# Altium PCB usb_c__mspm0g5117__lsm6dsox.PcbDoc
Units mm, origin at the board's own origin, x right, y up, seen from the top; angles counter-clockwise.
Board outline 92 x 60 mm, 2 copper layers (Top, Bottom), stack 0 mm thick; 35 components, 28 nets, 186 pads, 77 vias.
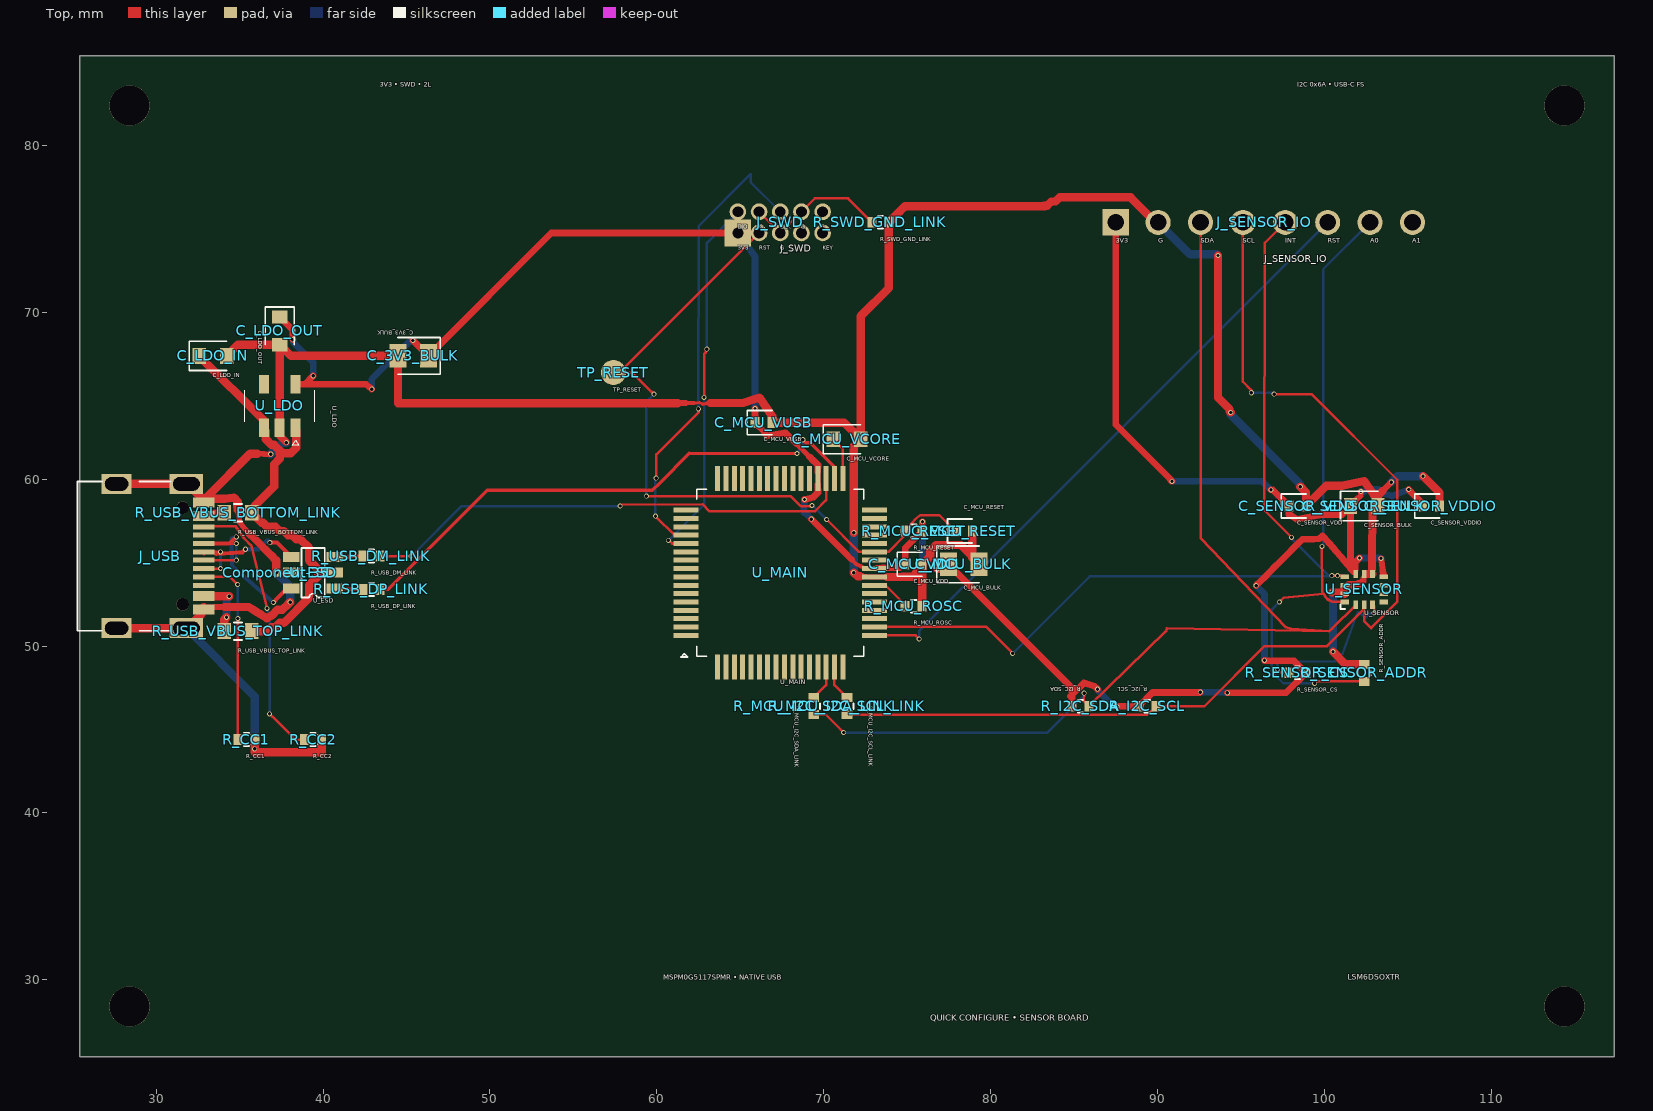
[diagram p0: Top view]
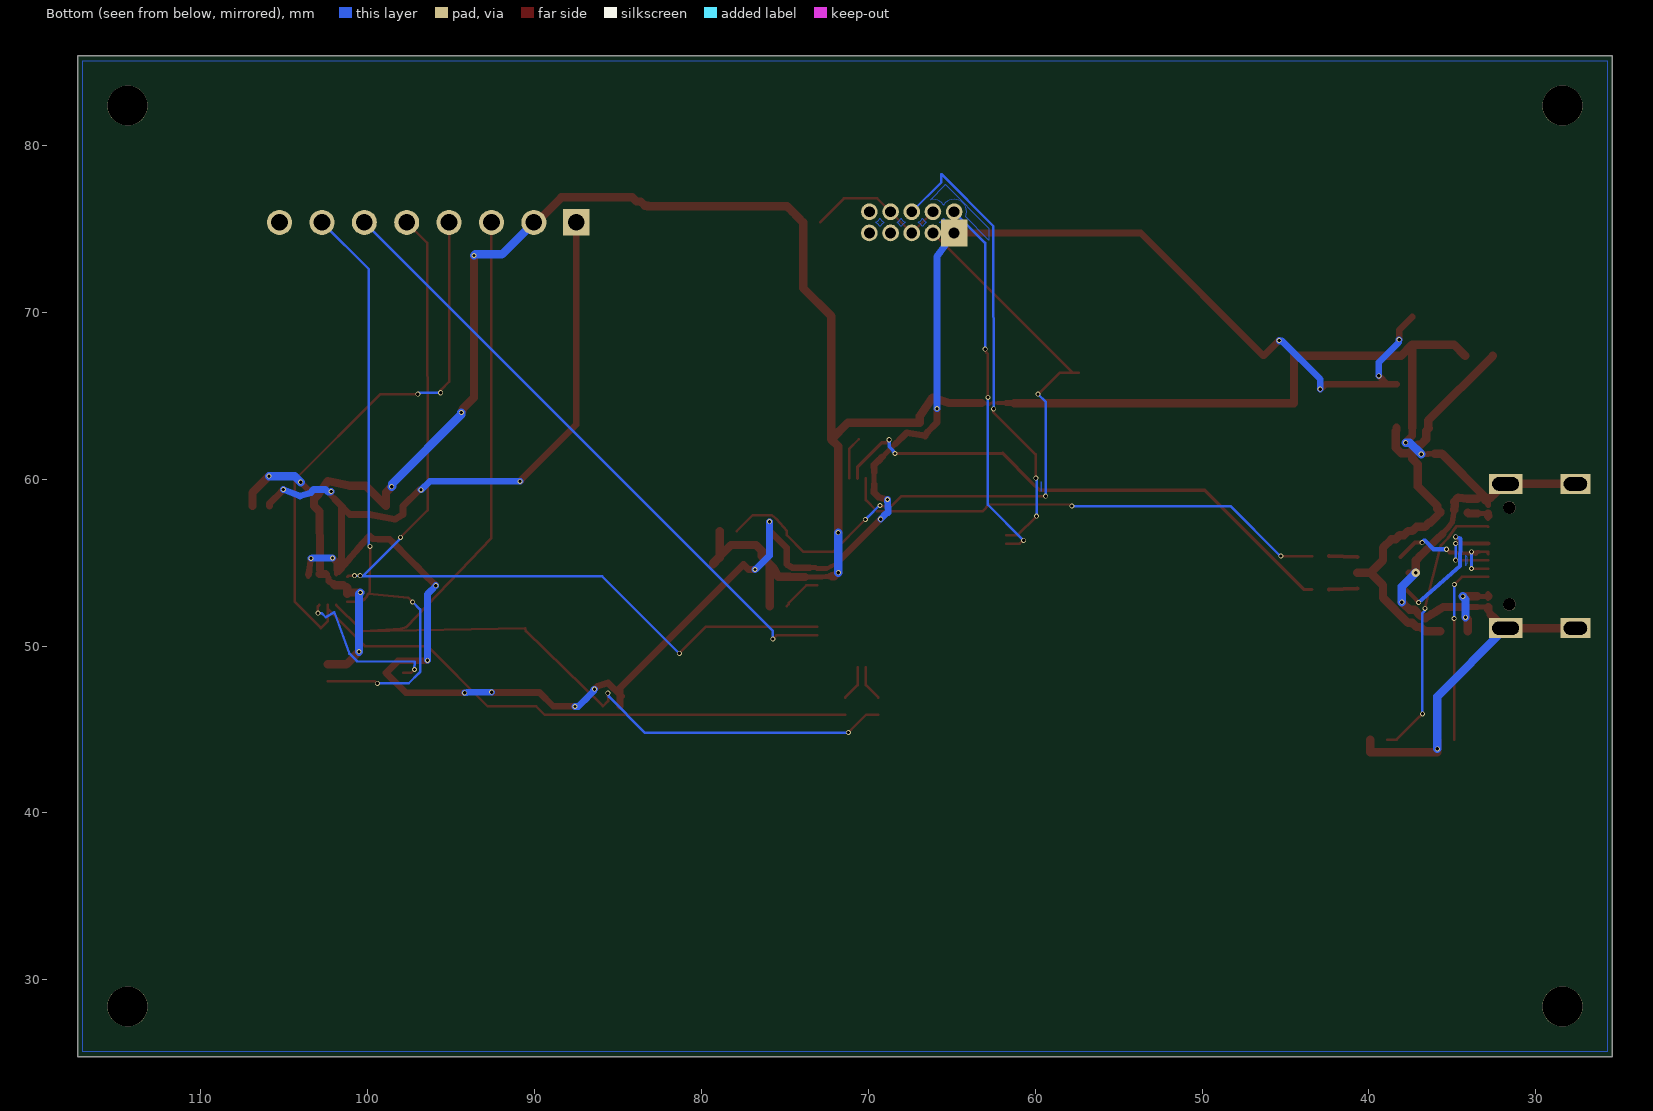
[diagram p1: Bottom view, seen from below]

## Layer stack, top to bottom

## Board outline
25.4,85.4 117.4,85.4 117.4,25.4 25.4,25.4

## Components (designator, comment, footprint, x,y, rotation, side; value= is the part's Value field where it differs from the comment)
C_3V3_BULK "" TSCIRCUIT-2.8500x1.4000mm 45.4,67.4 r180 top
C_LDO_IN "" TSCIRCUIT-2.4500x0.9500mm 33.4,67.4 r0 top
C_LDO_OUT "" TSCIRCUIT-0.9500x2.4500mm 37.4,68.9 r270 top
C_MCU_BULK "" TSCIRCUIT-2.8500x1.4000mm 78.4,54.9 r0 top
C_MCU_RESET "" TSCIRCUIT-1.5600x0.6400mm 78.4,56.9 r0 top
C_MCU_VCORE "" TSCIRCUIT-2.4500x0.9500mm 71.4,62.4 r0 top
C_MCU_VDD "" TSCIRCUIT-1.5600x0.6400mm 75.4,54.9 r0 top
C_MCU_VUSB "" TSCIRCUIT-1.5600x0.6400mm 66.4,63.4 r0 top
C_SENSOR_BULK "" TSCIRCUIT-2.4500x0.9500mm 102.4,58.4 r0 top
C_SENSOR_VDD "" TSCIRCUIT-1.5600x0.6400mm 98.4,58.4 r0 top
C_SENSOR_VDDIO "" TSCIRCUIT-1.5600x0.6400mm 106.4,58.4 r0 top
Component-35 "" TSCIRCUIT-0.5000x0.5000mm 37.2,54.4 r0 top
J_SENSOR_IO "" TSCIRCUIT-19.2800x1.5000mm 96.4,75.4 r0 top
J_SWD "" TSCIRCUIT-6.0800x2.2700mm 67.4,75.4 r0 top
J_USB "" TSCIRCUIT-6.7732x9.8502mm 30.113,55.4 r90 top
R_CC1 "" TSCIRCUIT-1.5600x0.6400mm 35.4,44.4 r0 top
R_CC2 "" TSCIRCUIT-1.5600x0.6400mm 39.4,44.4 r0 top
R_I2C_SCL "" TSCIRCUIT-1.5600x0.6400mm 89.4,46.4 r180 top
R_I2C_SDA "" TSCIRCUIT-1.5600x0.6400mm 85.4,46.4 r180 top
R_MCU_I2C_SCL_LINK "" TSCIRCUIT-0.6400x1.5600mm 71.4,46.4 r270 top
R_MCU_I2C_SDA_LINK "" TSCIRCUIT-0.6400x1.5600mm 69.4,46.4 r270 top
R_MCU_RESET "" TSCIRCUIT-1.5600x0.6400mm 75.4,56.9 r0 top
R_MCU_ROSC "" TSCIRCUIT-1.5600x0.6400mm 75.4,52.4 r0 top
R_SENSOR_ADDR "" TSCIRCUIT-0.6400x1.5600mm 102.4,48.4 r90 top
R_SENSOR_CS "" TSCIRCUIT-1.5600x0.6400mm 98.4,48.4 r0 top
R_SWD_GND_LINK "" TSCIRCUIT-1.5600x0.6400mm 73.4,75.4 r0 top
R_USB_DM_LINK "" TSCIRCUIT-1.5600x0.6400mm 42.9,55.4 r0 top
R_USB_DP_LINK "" TSCIRCUIT-1.5600x0.6400mm 42.9,53.4 r0 top
R_USB_VBUS_BOTTOM_LINK "" TSCIRCUIT-2.4500x0.9500mm 34.9,58 r0 top
R_USB_VBUS_TOP_LINK "" TSCIRCUIT-2.4500x0.9500mm 34.9,50.9 r0 top
TP_RESET "" TSCIRCUIT-1.5000x1.5000mm 57.4,66.4 r0 top
U_ESD "" TSCIRCUIT-3.6000x2.5000mm 39.4,54.4 r0 top
U_LDO "" TSCIRCUIT-2.5000x3.7000mm 37.4,64.4 r270 top
U_MAIN "" TSCIRCUIT-12.8000x12.8000mm 67.4,54.4 r0 top
U_SENSOR "" TSCIRCUIT-2.8499x2.3500mm 102.4,53.4 r0 top

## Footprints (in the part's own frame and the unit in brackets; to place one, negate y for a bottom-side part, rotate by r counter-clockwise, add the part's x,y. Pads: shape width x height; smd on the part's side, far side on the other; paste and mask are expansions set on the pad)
TSCIRCUIT-0.5000x0.5000mm [mm]
TSCIRCUIT-0.6400x1.5600mm [mm]
  rect 0.54x0.64 smd: 1(-0.51,0) 2(0.51,0)
  silkscreen extent -0.15,-0.38 0.15,0.38
TSCIRCUIT-0.9500x2.4500mm [mm]
  rect 0.8x0.95 smd: 1(-0.825,0) 2(0.825,0)
  silkscreen extent -1.43,-0.87 0.82,0.88
TSCIRCUIT-1.5000x1.5000mm [mm]
  round 1.5 smd: 1(0,0)
TSCIRCUIT-1.5600x0.6400mm [mm]
  rect 0.54x0.64 smd: 1(-0.51,0) 2(0.51,0)
  silkscreen extent -0.98,-0.72 0.51,0.72
TSCIRCUIT-2.4500x0.9500mm [mm]
  rect 0.8x0.95 smd: 1(-0.825,0) 2(0.825,0)
  silkscreen extent -1.42,-0.87 0.82,0.87
TSCIRCUIT-2.5000x3.7000mm [mm]
  rect 1.1x0.6 smd: 1(1.3,0.95) 2(1.3,0) 3(1.3,-0.95) 4(-1.3,-0.95) 5(-1.3,0.95)
  silkscreen extent -0.95,-2.1 2.35,2.1
TSCIRCUIT-2.8499x2.3500mm [mm]
  rect 0.5x0.28 smd: 1(-1.175,-0.75) 2(-1.175,-0.25) 3(-1.175,0.25) 4(-1.175,0.75) 8(1.175,0.75) 9(1.175,0.25) 10(1.175,-0.25) 11(1.175,-0.75)
  rect 0.28x0.5 smd: 5(-0.5,0.925) 6(0,0.925) 7(0.5,0.925) 12(0.5,-0.925) 13(0,-0.925) 14(-0.5,-0.925)
  silkscreen extent -1.42,-1.17 -1.14,-0.89
TSCIRCUIT-2.8500x1.4000mm [mm]
  rect 1.025x1.4 smd: 1(-0.913,0) 2(0.913,0)
  silkscreen extent -1.63,-1.1 0.91,1.1
TSCIRCUIT-3.6000x2.5000mm [mm]
  rect 1x0.6 smd: 1(-1.3,-0.95) 2(-1.3,0) 3(-1.3,0.95) 4(1.3,0.95) 5(1.3,0) 6(1.3,-0.95)
  silkscreen extent -0.7,-1.49 0.7,1.49
TSCIRCUIT-6.0800x2.2700mm [mm]
  rect 1.6x1.6 hole 0.65: 1(-2.54,-0.635)
  round 1 hole 0.65: 2(-2.54,0.635) 3(-1.27,0.635) 4(0,0.635) 5(1.27,0.635) 6(2.54,0.635) 7(2.54,-0.635) 8(1.27,-0.635) 9(0,-0.635) 10(-1.27,-0.635)
TSCIRCUIT-6.7732x9.8502mm [mm]
  rect 0.3x1.3 smd: 1(-3.35,-2.737) 2(-3.05,-2.737) 3(-2.55,-2.737) 4(-2.25,-2.737) 5(-1.75,-2.737) 6(-1.25,-2.737) 7(-0.75,-2.737) 8(-0.25,-2.737) 9(0.25,-2.737) 10(0.75,-2.737) 11(1.25,-2.737) 12(1.75,-2.737) 13(2.55,-2.737) 14(2.25,-2.737) 15(3.35,-2.737) 16(3.05,-2.737)
  rect 1.2x2 hole 0.8 slot 1.6 at 90 deg: 17(-4.325,-1.693) 18(4.325,-1.693)
  rect 1.2x1.8 hole 0.8 slot 1.4 at 90 deg: 19(4.325,2.487) 20(-4.325,2.487)
  round 0.75 hole 0.75 unplated: NPTH-1(-2.9,-1.468) NPTH-2(2.9,-1.468)
  silkscreen extent -4.47,-0.75 4.47,4.83
TSCIRCUIT-12.8000x12.8000mm [mm]
  rect 1.5x0.3 smd: 1(-5.65,-3.75) 2(-5.65,-3.25) 3(-5.65,-2.75) 4(-5.65,-2.25) 5(-5.65,-1.75) 6(-5.65,-1.25) 7(-5.65,-0.75) 8(-5.65,-0.25) 9(-5.65,0.25) 10(-5.65,0.75) 11(-5.65,1.25) 12(-5.65,1.75) 13(-5.65,2.25) 14(-5.65,2.75) 15(-5.65,3.25) 16(-5.65,3.75) 33(5.65,3.75) 34(5.65,3.25) 35(5.65,2.75) 36(5.65,2.25) 37(5.65,1.75) 38(5.65,1.25) 39(5.65,0.75) 40(5.65,0.25) 41(5.65,-0.25) 42(5.65,-0.75) 43(5.65,-1.25) 44(5.65,-1.75) 45(5.65,-2.25) 46(5.65,-2.75) 47(5.65,-3.25) 48(5.65,-3.75)
  rect 0.3x1.5 smd: 17(-3.75,5.65) 18(-3.25,5.65) 19(-2.75,5.65) 20(-2.25,5.65) 21(-1.75,5.65) 22(-1.25,5.65) 23(-0.75,5.65) 24(-0.25,5.65) 25(0.25,5.65) 26(0.75,5.65) 27(1.25,5.65) 28(1.75,5.65) 29(2.25,5.65) 30(2.75,5.65) 31(3.25,5.65) 32(3.75,5.65) 49(3.75,-5.65) 50(3.25,-5.65) 51(2.75,-5.65) 52(2.25,-5.65) 53(1.75,-5.65) 54(1.25,-5.65) 55(0.75,-5.65) 56(0.25,-5.65) 57(-0.25,-5.65) 58(-0.75,-5.65) 59(-1.25,-5.65) 60(-1.75,-5.65) 61(-2.25,-5.65) 62(-2.75,-5.65) 63(-3.25,-5.65) 64(-3.75,-5.65)
  silkscreen extent -5.95,-5.05 5,5
TSCIRCUIT-19.2800x1.5000mm [mm]
  rect 1.6x1.6 hole 1: 1(-8.89,0)
  round 1.5 hole 1: 2(-6.35,0) 3(-3.81,0) 4(-1.27,0) 5(1.27,0) 6(3.81,0) 7(6.35,0) 8(8.89,0)

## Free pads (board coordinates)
  round 2.4 hole 2.4 unplated: NPTH-3(28.4,28.4) NPTH-4(114.4,28.4) NPTH-5(28.4,82.4) NPTH-6(114.4,82.4)

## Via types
v1: diameter 0.3, hole 0.2, Top to Bottom, 76 vias
v2: diameter 0.5, hole 0.2, Top to Bottom, 1 vias

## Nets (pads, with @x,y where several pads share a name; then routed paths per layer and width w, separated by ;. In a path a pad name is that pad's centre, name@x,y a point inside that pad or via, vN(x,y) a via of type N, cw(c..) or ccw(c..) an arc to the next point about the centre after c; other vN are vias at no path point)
".J_SWD > .pin2 to .U_MAIN > .pin12": J_SWD.2 U_MAIN.12 | length 22.6
  Top w0.15: v1(60.695,56.338) 60.751,56.282 60.805,56.282 60.937,56.15 U_MAIN.12 ; v1(62.834,64.909) 62.831,67.499 62.93,67.599 62.93,67.73 v1(63,67.8)
  Bottom w0.15: v1(60.695,56.338) 62.831,58.474 62.835,64.87 v1(62.834,64.909) ; v1(63,67.8) 63,74.175 J_SWD.2
".J_SWD > .pin4 to .U_MAIN > .pin13": J_SWD.4 U_MAIN.13 | length 28.2
  Top w0.15: v1(59.922,57.788) 59.964,57.746 61.06,56.65 U_MAIN.13 ; v1(59.963,60.073) 59.977,61.488 62.5,64.012 v1(62.493,64.228)
  Bottom w0.15: v1(59.922,57.788) 59.922,59.975 59.966,60.019 59.966,60.048 v1(59.963,60.073) ; v1(62.493,64.228) 62.5,75.17 65.628,78.297 65.628,77.807 J_SWD.4
".U_MAIN > .pin42 to .R_MCU_ROSC > .pin1": R_MCU_ROSC.1 U_MAIN.42 | length 2.4
  Top w0.15: U_MAIN.42 73.719,53.65 74.769,52.6 74.769,52.521 R_MCU_ROSC.1
GND: C_3V3_BULK.2 C_LDO_IN.2 C_LDO_OUT.2 C_MCU_BULK.2 C_MCU_RESET.2 C_MCU_VCORE.2 C_MCU_VDD.2 C_MCU_VUSB.2 C_SENSOR_BULK.2 C_SENSOR_VDD.2 C_SENSOR_VDDIO.2 J_SENSOR_IO.2 J_USB.1 J_USB.2 J_USB.15 J_USB.16 J_USB.17 J_USB.18 J_USB.19 J_USB.20 R_CC1.2 R_CC2.2 R_MCU_ROSC.2 R_SENSOR_ADDR.2 R_SWD_GND_LINK.2 U_ESD.2 U_LDO.2 U_MAIN.41 U_SENSOR.2 U_SENSOR.3 U_SENSOR.6 U_SENSOR.7 | length 197.9
  Top w0.2: 62.225,64.568 62.55,64.6 62.75,64.5
  Top w0.225: 61.736,64.567 62.225,64.568 ; 62.75,64.5 63.203,64.569
  Top w0.275: J_USB.16 J_USB.15@33.04,58.641
  Top w0.28: U_SENSOR.2@100.975,53.218 101.157,53.218 U_SENSOR.2 ; U_SENSOR.3@101.225,53.51 U_SENSOR.3 101.475,53.65 ; U_SENSOR.6@102.363,54.075 U_SENSOR.6 U_SENSOR.6@102.54,54.325 ; U_SENSOR.7@102.865,54.575 102.865,54.36 U_SENSOR.7
  Top w0.3: J_USB.1@32.699,51.9 J_USB.1 J_USB.1@32.849,52.2 ; J_USB.15@32.699,58.9 J_USB.15 ; J_USB.2 J_USB.2@32.946,52.332 ; J_USB.16@32.849,58.6 J_USB.15 ; J_USB.15@32.999,58.9 J_USB.15 ; J_USB.2@33.037,52.35 33.13,52.35 33.224,52.35 33.318,52.35 33.412,52.35 33.499,52.35 ; J_USB.15@33.04,58.641 33.231,58.832 33.499,58.832 ; 72.3,54.18 72.425,54.18 72.55,54.18 72.775,54.15 U_MAIN.41 73.144,54.15 73.237,54.15 73.331,54.15 73.425,54.15 73.519,54.15 73.612,54.15 73.706,54.15 U_MAIN.41@73.8,54.15
  Top w0.301: J_USB.2@32.946,52.332 J_USB.2@33.037,52.35
  Top w0.325: J_USB.16 J_USB.16@32.849,58.6 ; 34.89,58.16 34.942,57.796 34.994,57.431 35.262,57.068 35.582,56.747
  Top w0.35: 36.051,61.533 36.457,61.518 v1(36.862,61.504) ; 61.247,64.567 61.736,64.567 ; 103.49,59.29 103.755,59.555 v1(104.029,59.829)
  Top w0.375: 33.499,52.35 33.505,52.35 33.599,52.35 34.083,52.349 ; v1@37.75,62.25 v1(37.8,62.2) ; 102.337,53.9 U_SENSOR.6@102.363,54.075
  Top w0.4: 37.2,54.4 U_ESD.2@37.6,54.4 ; 72.175,54.18 72.3,54.18 ; 102.043,53.723 102.337,53.9
  Top w0.45: 35.582,56.747 35.903,56.427 36.224,56.106 36.544,55.785 ; U_LDO.2 37.4,62.6 v1@37.75,62.25
  Top w0.475: 34.083,52.349 34.568,52.347 ; 36.544,55.785 36.865,55.464 ; U_MAIN.41@73.8,54.15 74.253,54.15 74.707,54.15
  Top w0.5: J_USB.20 J_USB.17 31.874,51.075 32.474,51.675 32.699,51.9 ; J_USB.19 J_USB.18 31.874,59.725 32.474,59.125 32.699,58.9 ; J_USB.1@32.849,52.2 J_USB.2 ; 32.999,58.9 35.632,61.533 36.051,61.533 ; 33.499,58.832 33.658,58.832 34.086,58.832 34.65,58.9 34.9,58.65 34.837,58.525 34.89,58.16 ; C_LDO_IN.2 34.9,68.075 C_LDO_OUT.2 ; 34.568,52.347 35.052,52.346 35.536,52.345 35.897,52.124 36.258,51.902 36.619,51.681 36.935,51.849 37.27,52.184 37.566,52.184 37.919,52.537 v1(38.023,52.641) ; v1(35.9,43.85) 35.9,43.904 35.91,43.914 R_CC1.2 35.91,43.65 39.91,43.65 R_CC2.2 ; 36.865,55.464 37.186,55.144 37.186,54.779 37.186,54.414 37.2,54.4 ; U_LDO.2 C_LDO_OUT.2 ; 61.247,64.567 60.758,64.566 60.26,64.566 59.763,64.566 59.265,64.566 58.767,64.566 58.27,64.566 57.772,64.566 57.274,64.566 56.777,64.566 56.279,64.566 55.781,64.566 55.284,64.566 54.786,64.566 54.288,64.566 53.791,64.566 53.293,64.566 52.795,64.567 52.298,64.567 51.8,64.567 51.302,64.567 50.805,64.567 50.307,64.567 49.809,64.567 44.488,64.567 C_3V3_BULK.2 38.075,67.4 C_LDO_OUT.2 ; 63.203,64.569 63.693,64.57 64.182,64.571 64.671,64.571 65.16,64.572 66.15,64.9 66.91,63.795 C_MCU_VUSB.2 71.225,63.4 C_MCU_VCORE.2 ; v1(71.8,54.4) 72.05,54.18 72.175,54.18 ; 74.707,54.15 75.4,54.15 75.66,54.65 C_MCU_VDD.2 ; R_MCU_ROSC.2 C_MCU_VDD.2 ; C_MCU_RESET.2 78.91,55.303 C_MCU_BULK.2 79.313,54.988 78.233,56.067 76.733,56.067 76.4,55.733 76.4,55.4 75.9,54.9 C_MCU_VDD.2 ; J_SENSOR_IO.2 89.9,75.4 88.4,76.9 84.15,76.9 83.9,76.65 83.65,76.65 83.4,76.4 83.202,76.4 83.235,76.366 82.748,76.366 82.261,76.366 81.773,76.366 81.286,76.366 80.799,76.366 80.311,76.366 79.824,76.366 79.337,76.366 78.849,76.366 78.362,76.366 77.875,76.366 77.387,76.366 76.9,76.366 76.413,76.366 75.925,76.366 75.438,76.366 74.951,76.366 74.876,76.366 74.554,76.044 74.232,75.722 R_SWD_GND_LINK.2 73.91,71.464 72.225,69.779 72.225,69.287 72.225,68.795 72.225,68.303 72.225,67.812 72.225,67.32 72.225,66.828 72.225,66.336 72.225,65.844 72.225,65.352 72.225,64.86 72.225,64.368 72.225,63.876 72.225,63.384 72.225,62.892 C_MCU_VCORE.2 ; v1(93.635,73.414) 93.635,64.894 94.327,64.202 94.327,64.073 v1(94.4,64) ; v1(98.573,59.555) 98.91,59.218 C_SENSOR_VDD.2 100.122,59.612 101.07,59.612 102.4,59.9 102.971,59.077 103.225,58.824 C_SENSOR_BULK.2 ; v1(100.449,53.218) 100.803,53.218 100.975,53.218 ; v1(100.528,49.67) 101.288,48.91 R_SENSOR_ADDR.2 ; U_SENSOR.2 101.225,53.29 101.225,53.51 ; 101.475,53.65 101.971,53.65 102.043,53.723 ; 102.54,54.325 102.76,54.325 U_SENSOR.7 ; 102.865,54.575 102.865,55.329 102.9,58.075 C_SENSOR_BULK.2 ; 103.49,59.29 103.225,59.025 103.225,58.712 C_SENSOR_BULK.2 ; v1(105.921,60.187) 106.91,59.198 C_SENSOR_VDDIO.2 ; v1(71.813,56.799) v1(71.813,56.799) ; v1(71.813,56.799) 71.814,56.82 71.814,61.989 C_MCU_VCORE.2
  Bottom w0.5: J_USB.17 35.9,46.981 v1(35.9,43.85) ; v1(36.862,61.504) 37.558,62.2 v1(37.8,62.2) ; 37.2,54.4 37.474,54.126 37.749,53.851 38.023,53.577 38.023,53.109 v1(38.023,52.641) ; v1(71.8,54.4) 71.8,54.556 71.813,54.569 v1(71.813,56.799) ; J_SENSOR_IO.2 91.965,73.485 93.485,73.485 93.564,73.485 v1(93.635,73.414) ; v1(94.4,64) 94.4,63.872 98.535,59.737 98.535,59.593 v1(98.573,59.555) ; v1(100.449,53.218) 100.528,53.139 v1(100.528,49.67) ; v1(104.029,59.829) 104.387,60.187 v1(105.921,60.187)
MAIN_RESET: C_MCU_RESET.1 J_SWD.10 R_MCU_RESET.1 TP_RESET.1 U_MAIN.38 | length 42.9
  Top w0.15: v1(59.376,58.985) 68.025,58.992 68.625,58.392 69.268,58.392 v1(69.302,58.433) ; v1(59.833,65.099) 59.687,65.245 59.679,65.245 58.524,66.4 TP_RESET.1 57.765,66.4 J_SWD.10 ; v1(70.186,57.593) 72.129,55.65 U_MAIN.38 73.889,55.65 74.889,56.651 R_MCU_RESET.1@74.889,56.899 ; R_MCU_RESET.1 75.505,57.62 75.787,57.859 76.931,57.859 C_MCU_RESET.1
  Bottom w0.15: v1(59.376,58.985) 59.362,59.006 59.362,59.046 59.362,64.628 v1(59.833,65.099) ; v1(69.302,58.433) 69.346,58.426 70.019,57.752 70.027,57.752 v1(70.186,57.593)
MCU_I2C_SCL_LOCAL: R_MCU_I2C_SCL_LINK.1 U_MAIN.50 | length 2.2
  Top w0.15: U_MAIN.50 70.65,47.66 R_MCU_I2C_SCL_LINK.1
MCU_I2C_SDA_LOCAL: R_MCU_I2C_SDA_LINK.1 U_MAIN.51 | length 2.2
  Top w0.15: R_MCU_I2C_SDA_LINK.1 70.15,47.66 U_MAIN.51
MSPM0_VCORE: C_MCU_VCORE.1 U_MAIN.32 | length 2.6
  Top w0.15: C_MCU_VCORE.1 71.15,61.825 U_MAIN.32
SENSOR_ADDR0: J_SENSOR_IO.7 R_SENSOR_ADDR.1 U_SENSOR.1 | length 39.5
  Top w0.15: v1(97.311,52.645) 97.567,52.901 99.975,53.15 100.088,52.925 100.425,52.7 U_SENSOR.1 100.491,52.65 100.219,52.773 99.876,53.265 v1(99.867,55.982) ; v1(99.428,47.776) 99.443,47.761 99.454,47.761 99.583,47.89 R_SENSOR_ADDR.1
  Bottom w0.15: v1(97.311,52.645) 97.295,52.629 96.868,52.202 96.868,52.058 96.865,48.457 96.932,48.39 97.549,47.776 v1(99.428,47.776) ; v1(99.867,55.982) 99.947,56.062 99.947,72.597 J_SENSOR_IO.7
SENSOR_ADDR1: J_SENSOR_IO.8
SENSOR_CS: R_SENSOR_CS.1 U_SENSOR.12 | length 9.6
  Top w0.15: v1(97.205,48.601) 97.217,48.583 97.4,48.4 R_SENSOR_CS.1 ; U_SENSOR.12 102.988,52.387 v1(102.988,51.982)
  Bottom w0.15: v1(97.205,48.601) 97.2,49.053 100.65,49.1 101.1,49.55 102,52.025 102.522,51.734 102.774,51.986 102.984,51.986 v1(102.988,51.982)
SENSOR_INT: J_SENSOR_IO.5 U_MAIN.47 U_SENSOR.4 | length 55.1
  Top w0.15: U_MAIN.47 79.754,51.15 81.201,49.703 v1(81.334,49.57) ; J_SENSOR_IO.5 96.44,74.171 96.423,58.159 96.441,58.12 98.004,56.557 v1(98.042,56.519) ; v1(100.461,54.227) U_SENSOR.4@101.148,54.227 ; v1(100.8,54.225) U_SENSOR.4@101.148,54.227 ; U_SENSOR.4@101.148,54.227 U_SENSOR.4 U_SENSOR.4@101.148,54.227
  Bottom w0.15: v1(81.334,49.57) 85.948,54.184 100.28,54.184 100.419,54.184 v1(100.461,54.227) ; v1(98.042,56.519) 98.042,56.447 100.288,54.201 100.436,54.201 v1(100.8,54.225)
SENSOR_RESET: J_SENSOR_IO.6 U_MAIN.48 | length 37.9
  Top w0.15: U_MAIN.48 75.511,50.65 75.715,50.446 v1(75.728,50.433)
  Bottom w0.15: v1(75.728,50.433) 75.728,50.918 J_SENSOR_IO.6
SENSOR_SCL: J_SENSOR_IO.4 R_I2C_SCL.1 R_MCU_I2C_SCL_LINK.2 U_SENSOR.13 | length 66.3
  Top w0.15: R_MCU_I2C_SCL_LINK.2 89.4,45.89 R_I2C_SCL.1 92.819,46.4 96.419,49.999 100.17,49.999 102.398,52.227 102.398,52.473 U_SENSOR.13 102.4,51.497 102.812,51.084 104.376,52.647 104.382,59.975 99.24,65.105 v1(97.005,65.105) ; J_SENSOR_IO.4 95.13,65.846 95.622,65.354 95.622,65.203 v1(95.637,65.188)
  Bottom w0.15: v1(95.637,65.188) 96.887,65.188 96.922,65.188 v1(97.005,65.105)
SENSOR_SDA: J_SENSOR_IO.3 R_I2C_SDA.1 R_MCU_I2C_SDA_LINK.2 U_SENSOR.14 | length 68.4
  Top w0.15: R_MCU_I2C_SDA_LINK.2 70.13,45.89 71.028,44.992 v1(71.2,44.82) ; v1(85.618,47.181) 85.6,46.71 R_I2C_SDA.1 90.525,50.9 90.571,51.061 100.312,50.9 ; J_SENSOR_IO.3 92.59,56.48 97.725,51.125 98.021,51.048 100.312,50.9 ; 100.312,50.9 100.486,51.057 U_SENSOR.14 100.474,51.049 100.312,50.9
  Bottom w0.15: v1(71.2,44.82) 83.407,44.82 85.558,46.971 85.558,47.158 v1(85.618,47.181)
swd-ground-1-to-2: J_SWD.3 J_SWD.5 J_SWD.9 R_SWD_GND_LINK.1 | length 8.8
  Top w0.15: J_SWD.3 J_SWD.9 J_SWD.5 69.481,76.846 71.471,76.846 71.471,76.819 R_SWD_GND_LINK.1
usb-dm-device: R_USB_DM_LINK.1 U_ESD.4 | length 1.7
  Top w0.25: U_ESD.4 R_USB_DM_LINK.1
usb-dm-mcu: R_USB_DM_LINK.2 U_MAIN.30 | length 29.8
  Top w0.15: R_USB_DM_LINK.2 v1(45.28,55.4) ; v1(57.8,58.4) 57.8,58.439 57.836,58.482 62.763,58.494 63.138,58.1 69.495,58.093 70.15,58.755 U_MAIN.30
  Bottom w0.15: v1(45.28,55.4) 45.353,55.473 45.373,55.473 48.3,58.4 v1(57.8,58.4)
usb-dm-port-tie: J_USB.7 J_USB.9 U_ESD.3 | length 9.2
  Top w0.15: J_USB.7 v1(33.85,54.65) ; J_USB.9@33.35,55.65 33.318,55.65 33.224,55.65 33.13,55.65 33.037,55.65 32.943,55.65 32.849,55.51 J_USB.9 v1(33.85,55.65)
  Top w0.175: J_USB.9@33.35,55.65 J_USB.9@33.412,55.65
  Top w0.212: J_USB.9@33.412,55.65 33.505,55.65
  Top w0.25: 33.505,55.65 33.599,55.532 35.17,55.628 35.296,55.777 35.322,55.777 v1(35.353,55.808) ; v1(36.811,56.205) 37.245,56.205 U_ESD.3
  Bottom w0.15: v1(33.85,54.65) v1(33.85,55.65)
  Bottom w0.25: v1(35.353,55.808) 36.12,55.808 36.637,56.326 36.69,56.326 v1(36.811,56.205)
usb-dp-device: R_USB_DP_LINK.1 U_ESD.6 | length 1.7
  Top w0.25: U_ESD.6 R_USB_DP_LINK.1
usb-dp-mcu: R_USB_DP_LINK.2 U_MAIN.31 | length 32.6
  Top w0.2: R_USB_DP_LINK.2 43.901,53.4 49.846,59.345 59.724,59.351 60.176,59.769 61.946,61.566 v1(68.401,61.546) ; v1(68.749,62.371) 68.92,62.2 69.202,62.2 70.65,60.753 U_MAIN.31
  Bottom w0.2: v1(68.401,61.546) 68.514,61.658 68.514,61.719 68.749,61.954 v1(68.749,62.371)
usb-dp-port-tie: J_USB.8 J_USB.10 U_ESD.1 | length 13.7
  Top w0.15: J_USB.8 v1(34.8,55.15) ; J_USB.10 v1(34.8,56.15)
  Top w0.25: J_USB.10 34.393,56.15 v1(34.8,56.557) ; v1(37.021,52.619) 37.138,52.738 37.138,52.755 37.833,53.45 U_ESD.1
  Bottom w0.15: v1(34.8,55.15) v1(34.8,56.15)
  Bottom w0.25: v1(34.8,56.557) 34.508,56.441 34.532,54.801 v1(37.021,52.619)
USB_CC1: J_USB.6 R_CC1.1 | length 11.6
  Top w0.15: J_USB.6 34.426,54.15 v1(34.88,53.696) ; v1(34.888,51.66) 34.95,51.598 34.89,51.539 R_CC1.1
  Bottom w0.15: v1(34.88,53.696) 34.923,53.653 34.923,53.644 34.888,53.609 v1(34.888,51.66)
USB_CC2: J_USB.12 R_CC2.1 | length 16.4
  Top w0.15: J_USB.12 32.874,57.175 34.761,57.175 35.275,56.453 35.687,56.041 v1(36.642,52.271) ; v1(36.789,45.942) 36.953,45.778 36.961,45.778 38.339,44.4 R_CC2.1
  Bottom w0.15: v1(36.642,52.271) 36.639,52.219 36.639,52.129 36.789,51.979 v1(36.789,45.942)
USB_VBUS_BOTTOM_LOCAL: J_USB.13 J_USB.14 R_USB_VBUS_BOTTOM_LINK.1 | length 1.5
  Top w0.3: J_USB.14 J_USB.14@32.849,57.8 ; J_USB.13 32.927,57.95 33.005,57.95 33.083,57.95 33.161,57.95 33.239,57.95 33.317,57.95 33.394,57.95 33.472,57.95 33.499,57.95
  Top w0.475: J_USB.13@32.849,57.8 J_USB.13 ; 33.499,57.95 R_USB_VBUS_BOTTOM_LINK.1@33.762,57.95
  Top w0.5: R_USB_VBUS_BOTTOM_LINK.1@33.762,57.95 34.025,57.95 R_USB_VBUS_BOTTOM_LINK.1
USB_VBUS_TOP_LOCAL: J_USB.3 J_USB.4 R_USB_VBUS_TOP_LINK.1 | length 4.2
  Top w0.3: J_USB.4 32.849,53 J_USB.3 32.849,52.99 33.499,52.99
  Top w0.5: 33.499,52.99 v1(34.366,52.99) ; R_USB_VBUS_TOP_LINK.1 34.075,51.597 34.112,51.634 v1(34.21,51.732)
  Bottom w0.5: v1(34.21,51.732) 34.21,52.798 34.339,52.928 34.339,52.963 v1(34.366,52.99)
VBUS5: C_LDO_IN.1 R_USB_VBUS_BOTTOM_LINK.2 R_USB_VBUS_TOP_LINK.2 U_ESD.5 U_LDO.1 U_LDO.3 | length 30.3
  Top w0.5: C_LDO_IN.1 36.45,63.525 U_LDO.3 ; R_USB_VBUS_TOP_LINK.2 36.142,50.9 36.558,50.9 36.65,50.9 36.9,51.15 37.15,51.15 37.4,51.4 37.65,51.4 39.15,52.9 39.15,53.65 39.9,54.4 ; U_LDO.1 38.35,62.95 38.4,62.9 38.4,61.9 38.067,61.567 37.567,61.567 37.067,62.067 ; U_LDO.3 36.417,63.067 36.4,63.067 U_LDO.3@36.567,62.9 ; U_LDO.3 36.45,63.017 U_LDO.3@36.567,62.9 ; 36.567,62.4 36.9,62.067 ; 36.567,62.4 U_LDO.3@36.567,62.9 ; 36.567,62.4 36.9,62.067 ; 36.567,62.4 U_LDO.3@36.567,62.9 ; 36.9,62.067 37.067,62.067 ; 36.9,62.067 37.067,62.067 ; 37.067,62.067 37.4,61.733 37.4,61.233 37.067,60.9 37.067,59.567 35.9,58.4 35.9,58.233 35.733,58.067 35.733,58.008 R_USB_VBUS_BOTTOM_LINK.2 36,57.725 36.276,57.449 36.325,57.4 36.4,57.4 36.65,57.15 37.15,57.15 37.4,56.9 37.65,56.9 37.9,56.65 38.15,56.65 38.4,56.4 38.65,56.4 39.15,55.9 39.15,55.15 39.9,54.4 ; 39.9,54.4 U_ESD.5 39.9,54.4
VCC_3V3: C_3V3_BULK.1 C_LDO_OUT.1 C_MCU_BULK.1 C_MCU_VDD.1 C_MCU_VUSB.1 C_SENSOR_BULK.1 C_SENSOR_VDD.1 C_SENSOR_VDDIO.1 J_SENSOR_IO.1 J_SWD.1 R_I2C_SCL.2 R_I2C_SDA.2 R_MCU_RESET.2 R_SENSOR_CS.2 U_LDO.5 U_MAIN.29 U_MAIN.40 U_SENSOR.5 U_SENSOR.8 | length 158.1
  Top w0.25: 71.681,55.188 71.95,54.919 72.223,54.785 U_MAIN.40@72.496,54.65
  Top w0.28: U_SENSOR.5@101.76,54.465 U_SENSOR.5 ; U_SENSOR.5@101.76,54.486 U_SENSOR.5 ; U_SENSOR.5@101.9,54.575 U_SENSOR.5 ; U_SENSOR.8@103.554,54.29 U_SENSOR.8
  Top w0.3: 68.63,61.889 68.885,61.624 69.14,61.36 ; U_MAIN.29@69.65,59.684 U_MAIN.29 ; U_MAIN.40@72.496,54.65 72.773,54.65 U_MAIN.40 ; 101.669,54.591 101.76,54.486 ; 101.9,54.575 101.9,54.697 101.9,55.069
  Top w0.302: U_MAIN.29 U_MAIN.29@69.651,60.44
  Top w0.306: U_MAIN.40 73.162,54.705 U_MAIN.40@73.509,54.704
  Top w0.312: 68.393,62.115 68.63,61.889
  Top w0.337: 101.992,58.817 102.2,59.025 v1(102.2,59.273)
  Top w0.35: v1(103.405,55.267) 103.462,54.895 103.518,54.522
  Top w0.375: 68.157,62.342 68.393,62.115 ; 71.411,55.458 71.681,55.188
  Top w0.387: U_MAIN.40@73.509,54.704 73.856,54.703
  Top w0.4: C_LDO_OUT.1 38.19,68.935 v1(38.19,68.365) ; v1(39.4,66.2) 39.395,66.195 38.9,65.7 U_LDO.5 42.587,65.7 42.771,65.516 42.802,65.516 v1(42.916,65.402) ; v1(45.38,68.315) 45.398,68.315 C_3V3_BULK.1 53.678,74.765 J_SWD.1 ; v1(65.89,64.233) 65.89,64.15 65.89,63.775 C_MCU_VUSB.1 66.091,63.199 66.293,62.997 66.494,62.796 66.6,62.6 67.684,62.796 67.92,62.569 68.157,62.342 ; v1(68.854,58.788) 69.4,58.933 69.667,59.2 U_MAIN.29@69.65,59.684 ; 69.14,61.36 69.396,61.095 69.4,61.133 69.667,60.867 U_MAIN.29@69.651,60.44 ; v1(69.258,57.611) 69.527,57.342 69.796,57.073 70.066,56.803 70.335,56.534 70.604,56.265 70.873,55.996 71.142,55.727 71.411,55.458 ; 73.856,54.703 74.203,54.701 74.55,54.7 C_MCU_VDD.1 74.89,55.88 R_MCU_RESET.2 75.91,57.148 75.91,57.397 75.908,57.399 75.908,57.455 v1(75.928,57.465) ; v1(76.791,54.592) 77.18,54.592 77.334,54.746 C_MCU_BULK.1 84.89,47.498 R_I2C_SDA.2 84.888,46.702 84.886,47.003 84.8,47 85.6,47.8 86.238,47.601 v1(86.416,47.423) ; J_SENSOR_IO.1 87.51,63.285 90.787,60.008 90.787,59.967 v1(90.879,59.875) ; v1(87.58,46.382) 87.585,46.388 87.645,46.388 87.657,46.4 87.965,46.4 88.274,46.4 88.582,46.4 R_I2C_SCL.2 89.707,47.217 92.55,47.217 v1(92.578,47.245) ; v1(94.2,47.204) 97.714,47.204 R_SENSOR_CS.2 98.672,48.638 98.433,48.877 98.195,49.115 97.847,49.115 97.5,49.115 97.152,49.115 96.805,49.115 v1@96.457,49.115 ; v1(95.92,53.63) 96.197,53.907 96.474,54.184 96.751,54.461 97.027,54.737 97.304,55.014 97.581,55.291 97.858,55.568 98.134,55.844 98.411,56.121 98.688,56.398 99.019,56.4 99.363,56.417 99.706,56.433 99.9,56.6 100.3,56.2 100.281,56.184 100.512,55.919 100.744,55.653 100.975,55.387 101.206,55.122 101.437,54.856 101.669,54.591 ; v1(96.423,49.149) v1@96.457,49.115 ; v1(96.815,59.37) 96.92,59.37 C_SENSOR_VDD.1 97.894,58.396 97.894,58.141 97.894,57.887 98.4,57.6 99.885,57.892 100.284,57.893 100.682,57.894 101.08,57.895 101.328,58.147 C_SENSOR_BULK.1 ; 101.76,54.465 101.575,54.65 C_SENSOR_BULK.1 ; 101.9,55.069 v1(102.115,55.284) ; 101.992,58.817 101.783,58.608 C_SENSOR_BULK.1 ; 103.518,54.522 U_SENSOR.8@103.554,54.29 ; v1(105.066,59.386) 105.113,59.339 105.113,59.328 105.372,59.069 105.631,58.81 105.89,58.551 C_SENSOR_VDDIO.1
  Bottom w0.4: v1(38.19,68.365) 38.21,68.345 38.21,68.206 39.4,67.016 v1(39.4,66.2) ; v1(42.916,65.402) 42.916,66.003 45.206,68.293 45.358,68.293 v1(45.38,68.315) ; J_SWD.1 65.89,73.339 65.89,72.943 65.89,72.547 65.89,72.151 65.89,71.755 65.89,71.359 65.89,70.964 65.89,70.568 65.89,70.172 65.89,69.776 65.89,69.38 65.89,68.984 65.89,68.588 65.89,68.192 65.89,67.796 65.89,67.4 65.89,67.004 65.89,66.608 65.89,66.212 65.89,65.817 65.89,65.421 65.89,65.025 65.89,64.629 v1(65.89,64.233) ; v1(68.854,58.788) 68.8,58 68.854,58.022 69.025,57.852 69.196,57.681 69.196,57.673 v1(69.258,57.611) ; v1(75.928,57.465) 75.927,57.126 75.926,56.786 75.925,56.447 75.925,56.107 75.924,55.768 75.923,55.428 76.192,55.159 76.462,54.89 76.731,54.62 76.762,54.62 v1(76.791,54.592) ; v1(86.416,47.423) 86.472,47.367 86.472,47.3 86.702,47.07 86.931,46.841 87.16,46.612 87.39,46.382 v1(87.58,46.382) ; v1(90.879,59.875) 96.29,59.875 v1(96.815,59.37) ; v1(92.578,47.245) 94.031,47.245 94.063,47.214 94.19,47.214 v1(94.2,47.204) ; v1(95.92,53.63) 96.049,53.501 96.049,53.493 96.236,53.306 96.423,53.119 96.423,52.722 96.423,52.325 96.423,51.928 96.423,51.531 96.423,51.134 96.423,50.737 96.423,50.34 96.423,49.943 96.423,49.546 v1(96.423,49.149) ; v1(102.115,55.284) 102.448,55.284 102.781,55.284 103.115,55.284 103.324,55.284 v1(103.405,55.267) ; v1(102.2,59.273) 102.244,59.231 102.381,59.231 102.536,59.386 102.898,59.386 103.259,59.386 103.35,59.3 103.4,59.2 104.061,59.002 v1(105.066,59.386)
pads on no net: J_SWD.6 J_SWD.7 J_SWD.8 J_USB.5 J_USB.11 J_USB.NPTH-1 J_USB.NPTH-2 U_LDO.4 U_MAIN.1 U_MAIN.2 U_MAIN.3 U_MAIN.4 U_MAIN.5 U_MAIN.6 U_MAIN.7 U_MAIN.8 U_MAIN.9 U_MAIN.10 U_MAIN.11 U_MAIN.14 U_MAIN.15 U_MAIN.16 U_MAIN.17 U_MAIN.18 U_MAIN.19 U_MAIN.20 U_MAIN.21 U_MAIN.22 U_MAIN.23 U_MAIN.24 U_MAIN.25 U_MAIN.26 U_MAIN.27 U_MAIN.28 U_MAIN.33 U_MAIN.34 U_MAIN.35 U_MAIN.36 U_MAIN.37 U_MAIN.39 U_MAIN.43 U_MAIN.44 U_MAIN.45 U_MAIN.46 U_MAIN.49 U_MAIN.52 U_MAIN.53 U_MAIN.54 U_MAIN.55 U_MAIN.56 U_MAIN.57 U_MAIN.58 U_MAIN.59 U_MAIN.60 U_MAIN.61 U_MAIN.62 U_MAIN.63 U_MAIN.64 U_SENSOR.9 U_SENSOR.10 U_SENSOR.11
copper on no net:
  other v2: 37.2,54.4

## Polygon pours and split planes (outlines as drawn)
GND on Bottom (solid): 117.1,85.1 25.7,85.1 25.7,25.7 117.1,25.7
GND on Bottom (solid): 59.637,59.843 59.637,59.286 59.647,59.278 59.647,59.831
GND on Bottom (solid): 65.495,75.64 65.484,75.618 65.399,75.515 65.591,75.515 65.506,75.618
GND on Bottom (solid): 65.61,75.496 65.61,75.304 65.713,75.389 65.735,75.4 65.713,75.411
GND on Bottom (solid): 69.305,75.64 69.294,75.618 69.2,75.505 69.087,75.411 69.065,75.4 69.087,75.389 69.2,75.295 69.294,75.182 69.305,75.16 69.316,75.182 69.41,75.295 69.523,75.389 69.545,75.4 69.523,75.411 69.41,75.505 69.316,75.618
GND on Bottom (solid): 68.035,75.64 68.024,75.618 67.93,75.505 67.817,75.411 67.795,75.4 67.817,75.389 67.93,75.295 68.024,75.182 68.035,75.16 68.046,75.182 68.14,75.295 68.253,75.389 68.275,75.4 68.253,75.411 68.14,75.505 68.046,75.618
GND on Bottom (solid): 66.765,75.64 66.754,75.618 66.66,75.505 66.547,75.411 66.525,75.4 66.547,75.389 66.66,75.295 66.754,75.182 66.765,75.16 66.776,75.182 66.87,75.295 66.983,75.389 67.005,75.4 66.983,75.411 66.87,75.505 66.776,75.618
GND on Bottom (solid): 65.391,77.671 62.775,75.056 62.775,74.332 62.806,74.369 64.173,75.737 64.167,75.748 64.124,75.889 64.11,76.035 64.124,76.181 64.167,76.322 64.236,76.452 64.33,76.565 64.443,76.659 64.573,76.728 64.714,76.771 64.86,76.785 65.006,76.771 65.147,76.728 65.277,76.659 65.39,76.565 65.484,76.452 65.495,76.43 65.506,76.452 65.6,76.565 65.713,76.659 65.843,76.728 65.984,76.771 66.13,76.785 66.275,76.771 65.434,77.612 65.4,77.654
GND on Bottom (solid): 34.198,55.456 34.183,55.428 34.133,55.367 34.125,55.361 34.125,54.939 34.133,54.933 34.183,54.872 34.207,54.827

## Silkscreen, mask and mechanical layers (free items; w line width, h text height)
Top Overlay:
  text "3V3 • SWD • 2L" at 43.4,83.4 h0.48
  text "I2C 0x6A • USB-C FS" at 98.4,83.4 h0.5
  text "MSPM0G5117SPMR • NATIVE USB" at 60.4,29.9 h0.52
  text "LSM6DSOXTR" at 101.4,29.9 h0.55
  text "QUICK CONFIGURE • SENSOR BOARD" at 76.4,27.4 h0.65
